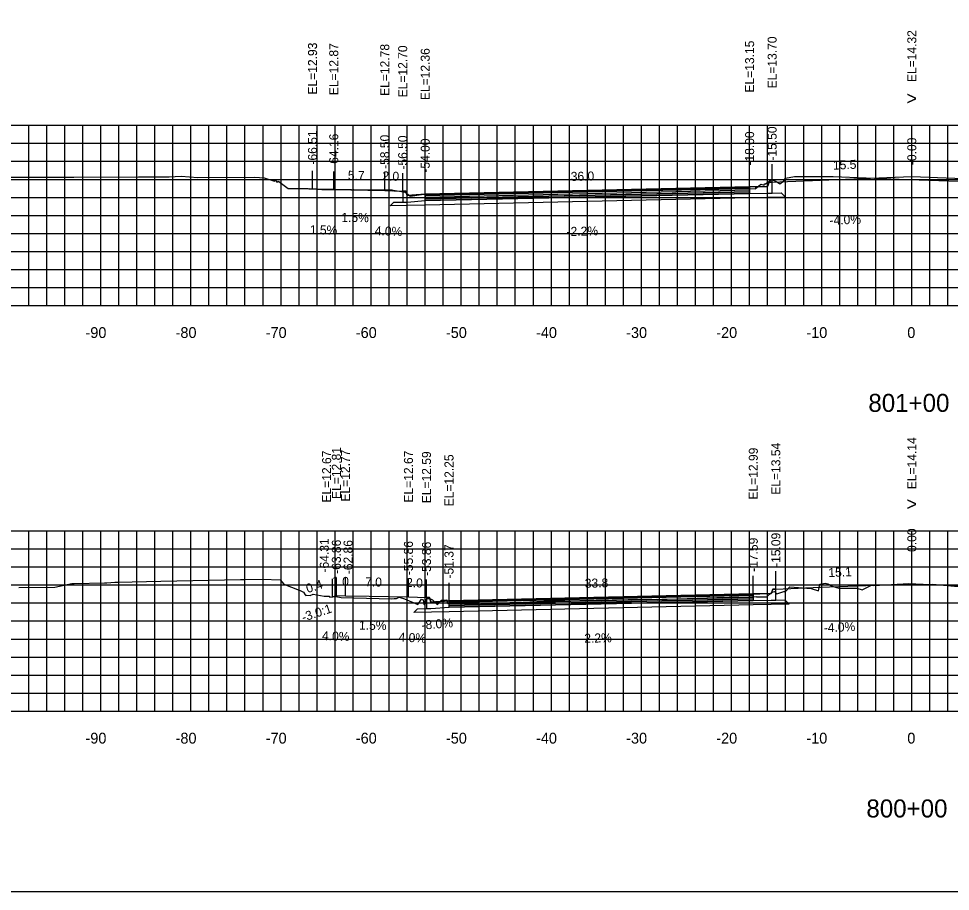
# Model space of a CAD drawing. Extents: x 1797419 to 1809236, y 248759 to 251512.
# Drawn here: x 1802191.9 to 1802295.3, y 250079.4 to 250176.3 of the extents above; entities that cross this region are included whole.
import ezdxf

# ---------------------------------------------------------------- set-up
doc = ezdxf.new("R2010")
doc.units = 0
for name, color, linetype in [('1', 7, 'Continuous'), ('10', 7, 'Continuous'), ('3', 7, 'Continuous'), ('4', 7, 'Continuous'), ('60', 7, 'Continuous'), ('BASE', 7, 'Continuous'), ('CL-CNST', 7, 'Continuous'), ('Level 62', 7, 'Continuous'), ('LOWER BINDER', 7, 'Continuous'), ('M-ROADS', 7, 'Continuous'), ('UPPER BINDER', 7, 'Continuous'), ('WEARING', 7, 'Continuous')]:
    doc.layers.add(name, color=color, linetype=linetype)

msp = doc.modelspace()

# ---------------------------------------------------------------- linework, layer by layer
for p, q in [((1802275.5, 250158.13), (1802275.5, 250160.13)), ((1802291, 250158.75), (1802291, 250160.75)), ((1802224.49, 250157.36), (1802224.49, 250159.36)), ((1802226.85, 250157.3), (1802226.85, 250159.3)), ((1802232.51, 250157.21), (1802232.51, 250159.21)), ((1802234.5, 250157.13), (1802234.5, 250159.13)), ((1802237, 250156.79), (1802237, 250158.79)), ((1802273, 250157.59), (1802273, 250159.59)), ((1802291, 250113.57), (1802291, 250115.57)), ((1802291, 250113.57), (1802291, 250115.57)), ((1802291.01, 250113.57), (1802291.01, 250115.57)), ((1802273.41, 250112.43), (1802273.41, 250114.43)), ((1802275.91, 250112.97), (1802275.91, 250114.97)), ((1802226.7, 250112.1), (1802226.7, 250114.1)), ((1802227.14, 250112.25), (1802227.14, 250114.25)), ((1802228.14, 250112.21), (1802228.14, 250114.21)), ((1802235.14, 250112.1), (1802235.14, 250114.1)), ((1802237.14, 250112.02), (1802237.14, 250114.02)), ((1802239.64, 250111.68), (1802239.64, 250113.68))]:
    msp.add_line(p, q)
for points in [[(1802141, 250079.43), (1802441, 250079.43), (1802441, 250269.43), (1802141, 250269.43)], [(1802275.5, 250158.13), (1802275.17, 250158.13), (1802275, 250157.63), (1802273, 250157.59), (1802273, 250156.87), (1802275, 250156.91), (1802275.5, 250156.91)], [(1802237, 250156.79), (1802235, 250156.63), (1802234.84, 250157.13), (1802234.5, 250157.13), (1802234.5, 250155.91), (1802235, 250155.91), (1802237, 250156.07)], [(1802275.91, 250112.97), (1802275.58, 250112.97), (1802275.41, 250112.47), (1802273.41, 250112.43), (1802273.41, 250111.71), (1802275.41, 250111.75), (1802275.91, 250111.75)], [(1802239.64, 250111.68), (1802237.64, 250111.52), (1802237.47, 250112.02), (1802237.14, 250112.02), (1802237.14, 250110.8), (1802237.64, 250110.8), (1802239.64, 250110.96)]]:
    msp.add_lwpolyline(points, close=True)
at = {"layer": '60'}
for p, q in [((1802141, 250144.43), (1802441, 250144.43)), ((1802201, 250144.37), (1802201, 250144.43)), ((1802211, 250144.37), (1802211, 250144.43)), ((1802221, 250144.37), (1802221, 250144.43)), ((1802231, 250144.37), (1802231, 250144.43)), ((1802241, 250144.37), (1802241, 250144.43)), ((1802251, 250144.37), (1802251, 250144.43)), ((1802261, 250144.37), (1802261, 250144.43)), ((1802271, 250144.37), (1802271, 250144.43)), ((1802281, 250144.37), (1802281, 250144.43)), ((1802291, 250144.37), (1802291, 250144.43)), ((1802141, 250099.43), (1802441, 250099.43)), ((1802201, 250099.37), (1802201, 250099.43)), ((1802211, 250099.37), (1802211, 250099.43)), ((1802221, 250099.37), (1802221, 250099.43)), ((1802231, 250099.37), (1802231, 250099.43)), ((1802241, 250099.37), (1802241, 250099.43)), ((1802251, 250099.37), (1802251, 250099.43)), ((1802261, 250099.37), (1802261, 250099.43)), ((1802271, 250099.37), (1802271, 250099.43)), ((1802281, 250099.37), (1802281, 250099.43)), ((1802291, 250099.37), (1802291, 250099.43))]:
    msp.add_line(p, q, dxfattribs=at)
at = {"layer": 'BASE'}
for points in [[(1802233.1, 250155.49), (1802233.51, 250155.89), (1802234.5, 250155.91), (1802235, 250155.91), (1802237, 250156.07), (1802273, 250156.87), (1802275, 250156.91), (1802275.5, 250156.91), (1802276.5, 250156.93), (1802276.98, 250156.45), (1802273, 250156.37), (1802237, 250155.57)], [(1802235.73, 250110.38), (1802236.14, 250110.78), (1802237.14, 250110.8), (1802237.64, 250110.8), (1802239.64, 250110.96), (1802273.41, 250111.71), (1802275.41, 250111.75), (1802275.91, 250111.75), (1802276.91, 250111.77), (1802277.39, 250111.29), (1802273.41, 250111.21), (1802239.64, 250110.46)]]:
    msp.add_lwpolyline(points, close=True, dxfattribs=at)
at = {"layer": 'CL-CNST'}
for points in [[(1802224.49, 250157.36), (1802224.5, 250157.36), (1802224.5, 250157.36), (1802225.51, 250157.32), (1802226.85, 250157.3), (1802232.51, 250157.21), (1802234.5, 250157.13), (1802234.84, 250157.13), (1802234.87, 250157.04), (1802235, 250156.63), (1802236.84, 250156.78), (1802237, 250156.79), (1802273, 250157.59), (1802275, 250157.63), (1802275.17, 250158.13), (1802275.46, 250158.13), (1802275.5, 250158.13), (1802277.19, 250158.2), (1802291, 250158.75), (1802304.35, 250158.22)], [(1802226.7, 250112.1), (1802227.14, 250112.25), (1802228.14, 250112.21), (1802230.78, 250112.17), (1802235.14, 250112.1), (1802237.14, 250112.02), (1802237.34, 250112.02), (1802237.47, 250112.02), (1802237.5, 250111.91), (1802237.64, 250111.52), (1802239.64, 250111.68), (1802273.41, 250112.43), (1802274.12, 250112.44), (1802275.41, 250112.47), (1802275.46, 250112.62), (1802275.58, 250112.97), (1802275.91, 250112.97), (1802280.87, 250113.17), (1802291, 250113.57), (1802291, 250113.57), (1802291.01, 250113.57), (1802302.15, 250113.15)]]:
    msp.add_lwpolyline(points, dxfattribs=at)
at = {"layer": 'Level 62'}
for p, q in [((1802141, 250164.43), (1802441, 250164.43)), ((1802193, 250144.43), (1802193, 250164.43)), ((1802195, 250144.43), (1802195, 250164.43)), ((1802197, 250144.43), (1802197, 250164.43)), ((1802199, 250144.43), (1802199, 250164.43)), ((1802201, 250144.43), (1802201, 250164.43)), ((1802203, 250144.43), (1802203, 250164.43)), ((1802205, 250144.43), (1802205, 250164.43)), ((1802207, 250144.43), (1802207, 250164.43)), ((1802209, 250144.43), (1802209, 250164.43)), ((1802211, 250144.43), (1802211, 250164.43)), ((1802213, 250144.43), (1802213, 250164.43)), ((1802215, 250144.43), (1802215, 250164.43)), ((1802217, 250144.43), (1802217, 250164.43)), ((1802219, 250144.43), (1802219, 250164.43)), ((1802221, 250144.43), (1802221, 250164.43)), ((1802223, 250144.43), (1802223, 250164.43)), ((1802225, 250144.43), (1802225, 250164.43)), ((1802227, 250144.43), (1802227, 250164.43)), ((1802229, 250144.43), (1802229, 250164.43)), ((1802231, 250144.43), (1802231, 250164.43)), ((1802233, 250144.43), (1802233, 250164.43)), ((1802235, 250144.43), (1802235, 250164.43)), ((1802237, 250144.43), (1802237, 250164.43)), ((1802239, 250144.43), (1802239, 250164.43)), ((1802241, 250144.43), (1802241, 250164.43)), ((1802243, 250144.43), (1802243, 250164.43)), ((1802245, 250144.43), (1802245, 250164.43)), ((1802247, 250144.43), (1802247, 250164.43)), ((1802249, 250144.43), (1802249, 250164.43)), ((1802251, 250144.43), (1802251, 250164.43)), ((1802253, 250144.43), (1802253, 250164.43)), ((1802255, 250144.43), (1802255, 250164.43)), ((1802257, 250144.43), (1802257, 250164.43)), ((1802259, 250144.43), (1802259, 250164.43)), ((1802261, 250144.43), (1802261, 250164.43)), ((1802263, 250144.43), (1802263, 250164.43)), ((1802265, 250144.43), (1802265, 250164.43)), ((1802267, 250144.43), (1802267, 250164.43)), ((1802269, 250144.43), (1802269, 250164.43)), ((1802271, 250144.43), (1802271, 250164.43)), ((1802273, 250144.43), (1802273, 250164.43)), ((1802275, 250144.43), (1802275, 250164.43)), ((1802277, 250144.43), (1802277, 250164.43)), ((1802279, 250144.43), (1802279, 250164.43)), ((1802281, 250144.43), (1802281, 250164.43)), ((1802283, 250144.43), (1802283, 250164.43)), ((1802285, 250144.43), (1802285, 250164.43)), ((1802287, 250144.43), (1802287, 250164.43)), ((1802289, 250144.43), (1802289, 250164.43)), ((1802291, 250144.43), (1802291, 250164.43)), ((1802293, 250144.43), (1802293, 250164.43)), ((1802295, 250144.43), (1802295, 250164.43)), ((1802141, 250162.43), (1802441, 250162.43)), ((1802141, 250160.43), (1802441, 250160.43)), ((1802141, 250158.43), (1802441, 250158.43)), ((1802141, 250156.43), (1802441, 250156.43)), ((1802141, 250154.43), (1802441, 250154.43)), ((1802141, 250152.43), (1802441, 250152.43)), ((1802141, 250150.43), (1802441, 250150.43)), ((1802141, 250148.43), (1802441, 250148.43)), ((1802141, 250146.43), (1802441, 250146.43)), ((1802141, 250144.43), (1802441, 250144.43)), ((1802141, 250119.43), (1802441, 250119.43)), ((1802193, 250099.43), (1802193, 250119.43)), ((1802195, 250099.43), (1802195, 250119.43)), ((1802197, 250099.43), (1802197, 250119.43)), ((1802199, 250099.43), (1802199, 250119.43)), ((1802201, 250099.43), (1802201, 250119.43)), ((1802203, 250099.43), (1802203, 250119.43)), ((1802205, 250099.43), (1802205, 250119.43)), ((1802207, 250099.43), (1802207, 250119.43)), ((1802209, 250099.43), (1802209, 250119.43)), ((1802211, 250099.43), (1802211, 250119.43)), ((1802213, 250099.43), (1802213, 250119.43)), ((1802215, 250099.43), (1802215, 250119.43)), ((1802217, 250099.43), (1802217, 250119.43)), ((1802219, 250099.43), (1802219, 250119.43)), ((1802221, 250099.43), (1802221, 250119.43)), ((1802223, 250099.43), (1802223, 250119.43)), ((1802225, 250099.43), (1802225, 250119.43)), ((1802227, 250099.43), (1802227, 250119.43)), ((1802229, 250099.43), (1802229, 250119.43)), ((1802231, 250099.43), (1802231, 250119.43)), ((1802233, 250099.43), (1802233, 250119.43)), ((1802235, 250099.43), (1802235, 250119.43)), ((1802237, 250099.43), (1802237, 250119.43)), ((1802239, 250099.43), (1802239, 250119.43)), ((1802241, 250099.43), (1802241, 250119.43)), ((1802243, 250099.43), (1802243, 250119.43)), ((1802245, 250099.43), (1802245, 250119.43)), ((1802247, 250099.43), (1802247, 250119.43)), ((1802249, 250099.43), (1802249, 250119.43)), ((1802251, 250099.43), (1802251, 250119.43)), ((1802253, 250099.43), (1802253, 250119.43)), ((1802255, 250099.43), (1802255, 250119.43)), ((1802257, 250099.43), (1802257, 250119.43)), ((1802259, 250099.43), (1802259, 250119.43)), ((1802261, 250099.43), (1802261, 250119.43)), ((1802263, 250099.43), (1802263, 250119.43)), ((1802265, 250099.43), (1802265, 250119.43)), ((1802267, 250099.43), (1802267, 250119.43)), ((1802269, 250099.43), (1802269, 250119.43)), ((1802271, 250099.43), (1802271, 250119.43)), ((1802273, 250099.43), (1802273, 250119.43)), ((1802275, 250099.43), (1802275, 250119.43)), ((1802277, 250099.43), (1802277, 250119.43)), ((1802279, 250099.43), (1802279, 250119.43)), ((1802281, 250099.43), (1802281, 250119.43)), ((1802283, 250099.43), (1802283, 250119.43)), ((1802285, 250099.43), (1802285, 250119.43)), ((1802287, 250099.43), (1802287, 250119.43)), ((1802289, 250099.43), (1802289, 250119.43)), ((1802291, 250099.43), (1802291, 250119.43)), ((1802293, 250099.43), (1802293, 250119.43)), ((1802295, 250099.43), (1802295, 250119.43)), ((1802141, 250117.43), (1802441, 250117.43)), ((1802141, 250115.43), (1802441, 250115.43)), ((1802141, 250113.43), (1802441, 250113.43)), ((1802141, 250111.43), (1802441, 250111.43)), ((1802141, 250109.43), (1802441, 250109.43)), ((1802141, 250107.43), (1802441, 250107.43)), ((1802141, 250105.43), (1802441, 250105.43)), ((1802141, 250103.43), (1802441, 250103.43)), ((1802141, 250101.43), (1802441, 250101.43)), ((1802141, 250099.43), (1802441, 250099.43))]:
    msp.add_line(p, q, dxfattribs=at)
at = {"layer": 'LOWER BINDER'}
for points in [[(1802237, 250156.26), (1802237, 250156.45), (1802273, 250157.25), (1802273, 250157.06)], [(1802237, 250156.07), (1802237, 250156.26), (1802273, 250157.06), (1802273, 250156.87)], [(1802239.64, 250111.15), (1802239.64, 250111.34), (1802273.41, 250112.09), (1802273.41, 250111.9)], [(1802239.64, 250110.96), (1802239.64, 250111.15), (1802273.41, 250111.9), (1802273.41, 250111.71)]]:
    msp.add_lwpolyline(points, close=True, dxfattribs=at)
at = {"layer": 'M-ROADS'}
for points in [[(1802190.27, 250158.67), (1802192.55, 250158.67), (1802194.64, 250158.67), (1802195.37, 250158.67), (1802197.99, 250158.68), (1802205.2, 250158.71), (1802206.83, 250158.71), (1802208.6, 250158.71), (1802209.91, 250158.78), (1802211.76, 250158.63), (1802218.09, 250158.68), (1802219.14, 250158.6), (1802220.28, 250158.21), (1802220.29, 250158.26), (1802220.29, 250158.27), (1802220.29, 250158.3), (1802220.34, 250158.22), (1802220.34, 250158.41), (1802220.43, 250158.27), (1802220.55, 250158.11), (1802220.67, 250158.21), (1802220.72, 250158.2), (1802220.75, 250158.19), (1802221.79, 250157.4), (1802223.96, 250157.4), (1802224.09, 250157.37), (1802224.11, 250157.38), (1802224.14, 250157.43), (1802224.15, 250157.38), (1802224.16, 250157.36), (1802224.16, 250157.36), (1802224.17, 250157.36), (1802224.23, 250157.36), (1802224.92, 250157.36), (1802226.13, 250157.34), (1802226.64, 250157.35), (1802227.04, 250157.35), (1802228.77, 250157.32), (1802228.9, 250157.28), (1802229.03, 250157.29), (1802229.1, 250157.26), (1802229.45, 250157.25), (1802230.94, 250157.25), (1802231.22, 250157.27), (1802233.21, 250157.28), (1802233.33, 250157.28), (1802233.36, 250157.11), (1802233.44, 250157.22), (1802234.58, 250157.06), (1802234.65, 250157.06), (1802234.66, 250157.06), (1802234.69, 250157.03), (1802234.7, 250157.06), (1802234.74, 250157.05), (1802234.74, 250157.05), (1802235.31, 250156.59), (1802235.32, 250156.58), (1802235.32, 250156.59), (1802235.34, 250156.56), (1802236.86, 250156.78), (1802236.86, 250156.78), (1802236.88, 250156.78), (1802236.91, 250156.79), (1802236.92, 250156.8), (1802236.97, 250156.78), (1802237.3, 250156.79), (1802238.05, 250156.81), (1802244.78, 250156.88), (1802247.01, 250156.91), (1802249.52, 250156.95), (1802249.56, 250156.99), (1802259.56, 250157.19), (1802260.76, 250157.21), (1802261.19, 250157.22), (1802261.31, 250157.21), (1802269.59, 250157.35), (1802270.7, 250157.37), (1802270.94, 250157.39), (1802272.06, 250157.4), (1802272.24, 250157.41), (1802272.41, 250157.41), (1802272.55, 250157.4), (1802273.63, 250157.38), (1802273.65, 250157.39), (1802273.66, 250157.37), (1802273.7, 250157.54), (1802273.73, 250157.45), (1802274.24, 250157.89), (1802274.61, 250157.79), (1802274.67, 250157.94), (1802274.76, 250157.94), (1802274.76, 250157.95), (1802275.44, 250158.42), (1802275.91, 250158.21), (1802276.34, 250157.95), (1802276.81, 250158.25), (1802276.97, 250158.56), (1802277.97, 250158.74), (1802278.61, 250158.74), (1802279.75, 250158.74), (1802280.18, 250158.74), (1802282.28, 250158.74), (1802289.61, 250158.45), (1802298.41, 250158.17)], [(1802191.91, 250113.16), (1802195.91, 250113.17), (1802197.79, 250113.6), (1802198.06, 250113.58), (1802201.41, 250113.68), (1802201.66, 250113.68), (1802202.55, 250113.74), (1802202.89, 250113.75), (1802207.65, 250113.86), (1802216.51, 250114.05), (1802216.93, 250114.04), (1802218.95, 250114.07), (1802220.89, 250113.99), (1802221.3, 250113.5), (1802223.01, 250112.85), (1802223.11, 250112.83), (1802223.48, 250112.62), (1802223.68, 250112.35), (1802223.75, 250112.27), (1802223.86, 250112.28), (1802224.25, 250112.26), (1802224.56, 250112.4), (1802225.79, 250112.17), (1802226.35, 250112.18), (1802226.4, 250112.06), (1802227.07, 250112.15), (1802227.68, 250112.03), (1802233.28, 250111.88), (1802233.54, 250111.94), (1802233.68, 250111.92), (1802233.8, 250111.91), (1802234.1, 250112.08), (1802234.7, 250111.89), (1802236.18, 250111.27), (1802236.59, 250111.84), (1802236.76, 250111.79), (1802236.84, 250111.25), (1802237.16, 250111.51), (1802237.16, 250111.84), (1802237.3, 250111.91), (1802237.66, 250111.86), (1802237.8, 250111.76), (1802238.28, 250111.3), (1802238.29, 250111.28), (1802238.32, 250111.27), (1802238.34, 250111.27), (1802238.41, 250111.29), (1802238.79, 250111.74), (1802239.41, 250111.76), (1802239.48, 250111.38), (1802239.57, 250111.39), (1802239.58, 250111.41), (1802239.58, 250111.42), (1802239.58, 250111.41), (1802239.59, 250111.41), (1802239.64, 250111.46), (1802239.65, 250111.43), (1802239.83, 250111.4), (1802240.13, 250111.39), (1802240.28, 250111.44), (1802242.35, 250111.27), (1802250.94, 250111.67), (1802252.38, 250111.66), (1802259.53, 250111.81), (1802260.69, 250111.83), (1802261.55, 250111.82), (1802262.72, 250111.85), (1802262.74, 250111.83), (1802269.35, 250112.02), (1802270.73, 250112.07), (1802272.94, 250112.11), (1802273.41, 250112.14), (1802273.78, 250112.11), (1802273.79, 250112.15), (1802273.82, 250112.12), (1802274.02, 250112.1), (1802274.9, 250112.1), (1802274.96, 250112.13), (1802274.96, 250112.16), (1802275.36, 250112.5), (1802275.5, 250112.62), (1802275.76, 250112.69), (1802276.02, 250112.43), (1802276.81, 250112.71), (1802276.98, 250112.69), (1802277.47, 250113.21), (1802279.84, 250113.04), (1802280.66, 250112.76), (1802280.81, 250113.51), (1802281.37, 250113.64), (1802281.68, 250113.56), (1802282.17, 250113.29), (1802282.89, 250113.08), (1802284.69, 250113.08), (1802284.89, 250113.08), (1802285.5, 250112.89), (1802286.54, 250113.39), (1802286.77, 250113.38), (1802290.68, 250113.59), (1802293.04, 250113.49), (1802293.31, 250113.51), (1802296.13, 250113.25)]]:
    msp.add_lwpolyline(points, dxfattribs=at)
at = {"layer": 'UPPER BINDER'}
for points in [[(1802273, 250157.44), (1802237, 250156.64), (1802237, 250156.45), (1802273, 250157.25)], [(1802273.41, 250112.28), (1802239.64, 250111.53), (1802239.64, 250111.34), (1802273.41, 250112.09)]]:
    msp.add_lwpolyline(points, close=True, dxfattribs=at)
at = {"layer": 'WEARING'}
for points in [[(1802273, 250157.59), (1802237, 250156.79), (1802237, 250156.64), (1802273, 250157.44)], [(1802273.41, 250112.43), (1802239.64, 250111.68), (1802239.64, 250111.53), (1802273.41, 250112.28)]]:
    msp.add_lwpolyline(points, close=True, dxfattribs=at)

# ---------------------------------------------------------------- texts
msp.add_text('-3.0:1', height=1, rotation=18.3232).set_placement((1802223.48, 250109.33))
at = {"layer": '1'}
for s, p in [('801+00', (1802286.18, 250132.63)), ('800+00', (1802285.96, 250087.63))]:
    msp.add_text(s, height=2, dxfattribs=at).set_placement(p)
at = {"layer": '10'}
for s, p in [('-90', (1802199.3, 250140.83)), ('-80', (1802209.3, 250140.83)), ('-70', (1802219.3, 250140.83)), ('-60', (1802229.3, 250140.83)), ('-50', (1802239.3, 250140.83)), ('-40', (1802249.3, 250140.83)), ('-30', (1802259.3, 250140.83)), ('-20', (1802269.3, 250140.83)), ('-10', (1802279.3, 250140.83)), ('0', (1802290.5, 250140.83)), ('-90', (1802199.3, 250095.83)), ('-80', (1802209.3, 250095.83)), ('-70', (1802219.3, 250095.83)), ('-60', (1802229.3, 250095.83)), ('-50', (1802239.3, 250095.83)), ('-40', (1802249.3, 250095.83)), ('-30', (1802259.3, 250095.83)), ('-20', (1802269.3, 250095.83)), ('-10', (1802279.3, 250095.83)), ('0', (1802290.5, 250095.83))]:
    msp.add_text(s, height=1.2, dxfattribs=at).set_placement(p)
at = {"layer": '3'}
for s, p in [('EL=14.32', (1802291.5, 250169.22)), ('EL=12.93', (1802224.99, 250167.84)), ('EL=12.93', (1802225, 250167.83)), ('EL=12.93', (1802225, 250167.83)), ('EL=12.87', (1802227.35, 250167.77)), ('EL=12.78', (1802233.01, 250167.69)), ('EL=13.15', (1802273.5, 250168.06)), ('EL=13.70', (1802276, 250168.52)), ('EL=12.70', (1802235, 250167.53)), ('EL=12.36', (1802237.5, 250167.22)), ('-15.50', (1802276, 250160.51)), ('-66.51', (1802224.99, 250160.07)), ('-64.16', (1802227.35, 250159.71)), ('-58.50', (1802233.01, 250159.59)), ('-56.50', (1802235, 250159.51)), ('-18.00', (1802273.5, 250159.96)), ('-0.00', (1802291.5, 250160.01)), ('-54.00', (1802237.5, 250159.17)), ('EL=13.54', (1802276.41, 250123.44)), ('EL=14.14', (1802291.51, 250124.05)), ('EL=12.67', (1802226.56, 250122.57)), ('EL=12.81', (1802227.64, 250122.97)), ('EL=12.77', (1802228.64, 250122.68)), ('EL=12.67', (1802235.64, 250122.57)), ('EL=12.59', (1802237.64, 250122.49)), ('EL=12.25', (1802240.14, 250122.15)), ('EL=12.99', (1802273.91, 250122.9)), ('0.00', (1802291.5, 250117.09)), ('-64.31', (1802226.3, 250114.81)), ('-17.59', (1802273.91, 250114.88)), ('-15.09', (1802276.41, 250115.43)), ('-63.86', (1802227.64, 250114.66)), ('-62.86', (1802228.94, 250114.62)), ('-55.86', (1802235.64, 250114.51)), ('-53.86', (1802237.64, 250114.43)), ('-51.37', (1802240.14, 250114.14))]:
    msp.add_text(s, height=1, rotation=90, dxfattribs=at).set_placement(p)
at = {"layer": '4'}
for s, rotation, p in [('15.5', 2.2906, (1802282.27, 250159.5)), ('5.7', 359.1406, (1802228.41, 250158.38)), ('2.0', 357.709, (1802232.23, 250158.33)), ('36.0', 1.2603, (1802253.16, 250158.25)), ('1.5%', 359.1406, (1802227.69, 250153.72)), ('-4.0%', 2.2906, (1802281.89, 250153.38)), ('1.5%', 359.1406, (1802224.19, 250152.34)), ('4.0%', 357.709, (1802231.39, 250152.25)), ('-2.2%', 1.2603, (1802252.7, 250152.14)), ('15.1', 2.2877, (1802281.76, 250114.3)), ('1.0', 357.7094, (1802226.65, 250113.38)), ('0.4', 18.3232, (1802223.96, 250112.51)), ('7.0', 359.1406, (1802230.33, 250113.27)), ('2.0', 357.7094, (1802234.86, 250113.21)), ('33.8', 1.262, (1802254.72, 250113.11)), ('1.5%', 359.1406, (1802229.65, 250108.47)), ('-8.0%', 4.574, (1802236.63, 250108.47)), ('-4.0%', 2.2877, (1802281.25, 250108.18)), ('4.0%', 357.7094, (1802225.53, 250107.31)), ('4.0%', 357.7094, (1802234.03, 250107.14)), ('-2.2%', 1.262, (1802254.22, 250107))]:
    msp.add_text(s, height=1, rotation=rotation, dxfattribs=at).set_placement(p)
at = {"layer": '60'}
for p in [(1802290.39, 250166.68), (1802290.39, 250121.68)]:
    msp.add_text('>', height=1.5, dxfattribs=at).set_placement(p)

doc.saveas('drawing.dxf')
